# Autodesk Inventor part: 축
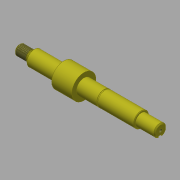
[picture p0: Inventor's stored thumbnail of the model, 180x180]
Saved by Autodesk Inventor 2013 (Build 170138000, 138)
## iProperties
Created: 2016-08
Part Number: 축
Material: 강철, 탄소
Document SubType Name: Modeling
Designer: mduedu
Density: 7.87 g/cm^3
Author: mduedu
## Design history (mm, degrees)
sketch "스케치1"
  geometry: L1 (-70, 0)-(70, 0); L2 (-70, 0)-(-70, 5); L3 (-70, 5)-(-56, 5); L4 (-56, 5)-(-56, 7.5); L5 (-56, 7.5)-(51, 7.5); L6 (51, 7.5)-(51, 6); L7 (51, 6)-(70, 6); L8 (70, 6)-(70, 0); 2 further points
  constraints: 16 end point, 5 parallel, 2 perpendicular, 1 coincident, 1 horizontal, 1 midpoint
  dimensions: "d0" = 140 distance of L1.start L1.end; "d2" = 14 distance of L2.end L3.end; "d3" = 19 distance of L6.end L7.end; "d4" = 10 diameter of L3 L1; "d5" = 15 diameter of L5 L1; "d6" = 12 diameter of L7 L1
revolve "회전1" sketch "스케치1" stored, may be unused: angle "d7" = 90 deg
sketch "스케치2"
  geometry: L1 (-56, -5)-(-56, 5) reference; L2 (70, -6)-(70, 6) reference; L3 (-56, 0)-(70, 0); L4 (-58, 4.5)-(-58, 5); L5 (-58, 5)-(-56, 5); L6 (-56, 5)-(-56, 4.5); L7 (-58, 4.5)-(-56, 4.5); 1 further point
  constraints: 10 end point, 2 midpoint, 1 parallel, 1 perpendicular, 1 point on line
  dimensions: "d8" = 2 distance of L4.end L5.end; "d10" = 10 diameter of L5 L3; "d11" = 9 diameter of L7 L3
revolve "회전2" sketch "스케치2" stored, may be unused: angle "d12" = 90 deg
node "작업 평면1"
sketch "스케치3"
  geometry: C1 r 12 at (0, 0); 1 further point
  constraints: 1 centre point, 1 coincident
  dimensions: "d15" = 24 diameter of C1
extrude "돌출1" join sketch "스케치3" distance "d16" = 20; taper "d17" = 0 deg
sketch "스케치5"
  geometry: L1 (-70, -5)-(-70, 5) reference; L2 (70, -6)-(70, 6) reference; L3 (-70, 0)-(70, 0); L4 (-6, 7.5)-(51, 7.5) reference; L5 (15.15, 7.5)-(14, 7.5); L6 (14, 7.5)-(14, 7.15); L7 (14, 7.15)-(15.15, 7.15); L8 (15.15, 7.15)-(15.15, 7.5); 1 further point
  constraints: 10 end point, 2 midpoint, 2 parallel, 1 horizontal, 1 perpendicular, 1 point on line
  dimensions: "d19" = 56 distance between parallel lines of L6 L2; "d20" = 1.15 distance between parallel lines of L8 L6; "d21" = 14.3 diameter of L7 L3
revolve "회전3" sketch "스케치5" stored, may be unused: angle "d22" = 90 deg
node "작업 평면3"
sketch "스케치6"
  geometry: L1 (6.5, 2)-(-9.5, 2); L2 (-9.5, 2)-(-9.5, -2); L3 (-9.5, -2)-(6.5, -2); L4 (-9.5, 6)-(-9.5, -6) reference; A1 r 2 centre (6.5, 0) between (6.5, -2) and (6.5, 2); 2 further points
  constraints: 6 end point, 2 midpoint, 2 point on circle, 2 tangent, 1 centre point, 1 horizontal, 1 horizontal alignment, 1 parallel, 1 perpendicular
  dimensions: "d23" = 4 distance between parallel lines of L3 L1; "d62" = 18 dimension on A1 L2
extrude "돌출2" cut sketch "스케치6" distance "d25" = 2.5; taper "d26" = 0 deg
feature "스레드1" dims "d27" = 10, "d28" = 0
chamfer "모따기5" distance "d41" = 0.5; stored, may be unused: second distance "d42" = 2, angle "d43" = 45 deg
chamfer "모따기6" distance "d44" = 0.5; stored, may be unused: second distance "d45" = 2, angle "d46" = 45 deg
chamfer "모따기7" distance "d47" = 1; stored, may be unused: second distance "d48" = 2, angle "d49" = 45 deg
chamfer "모따기8" distance "d50" = 1; stored, may be unused: second distance "d51" = 2, angle "d52" = 45 deg
sketch "스케치8"
  geometry: 1 further point
hole "구멍1" sketch "스케치8" at (2, 3.5) diameter "d53" = 3.242; stored, may be unused: countersink angle "d57" = 90 deg, drill point angle "d59" = 120 deg; dims "d54" = 10, "d55" = 4, "d56" = 2, "d58" = 12
node "솔리드1"
other parameters: "d13" = -44
